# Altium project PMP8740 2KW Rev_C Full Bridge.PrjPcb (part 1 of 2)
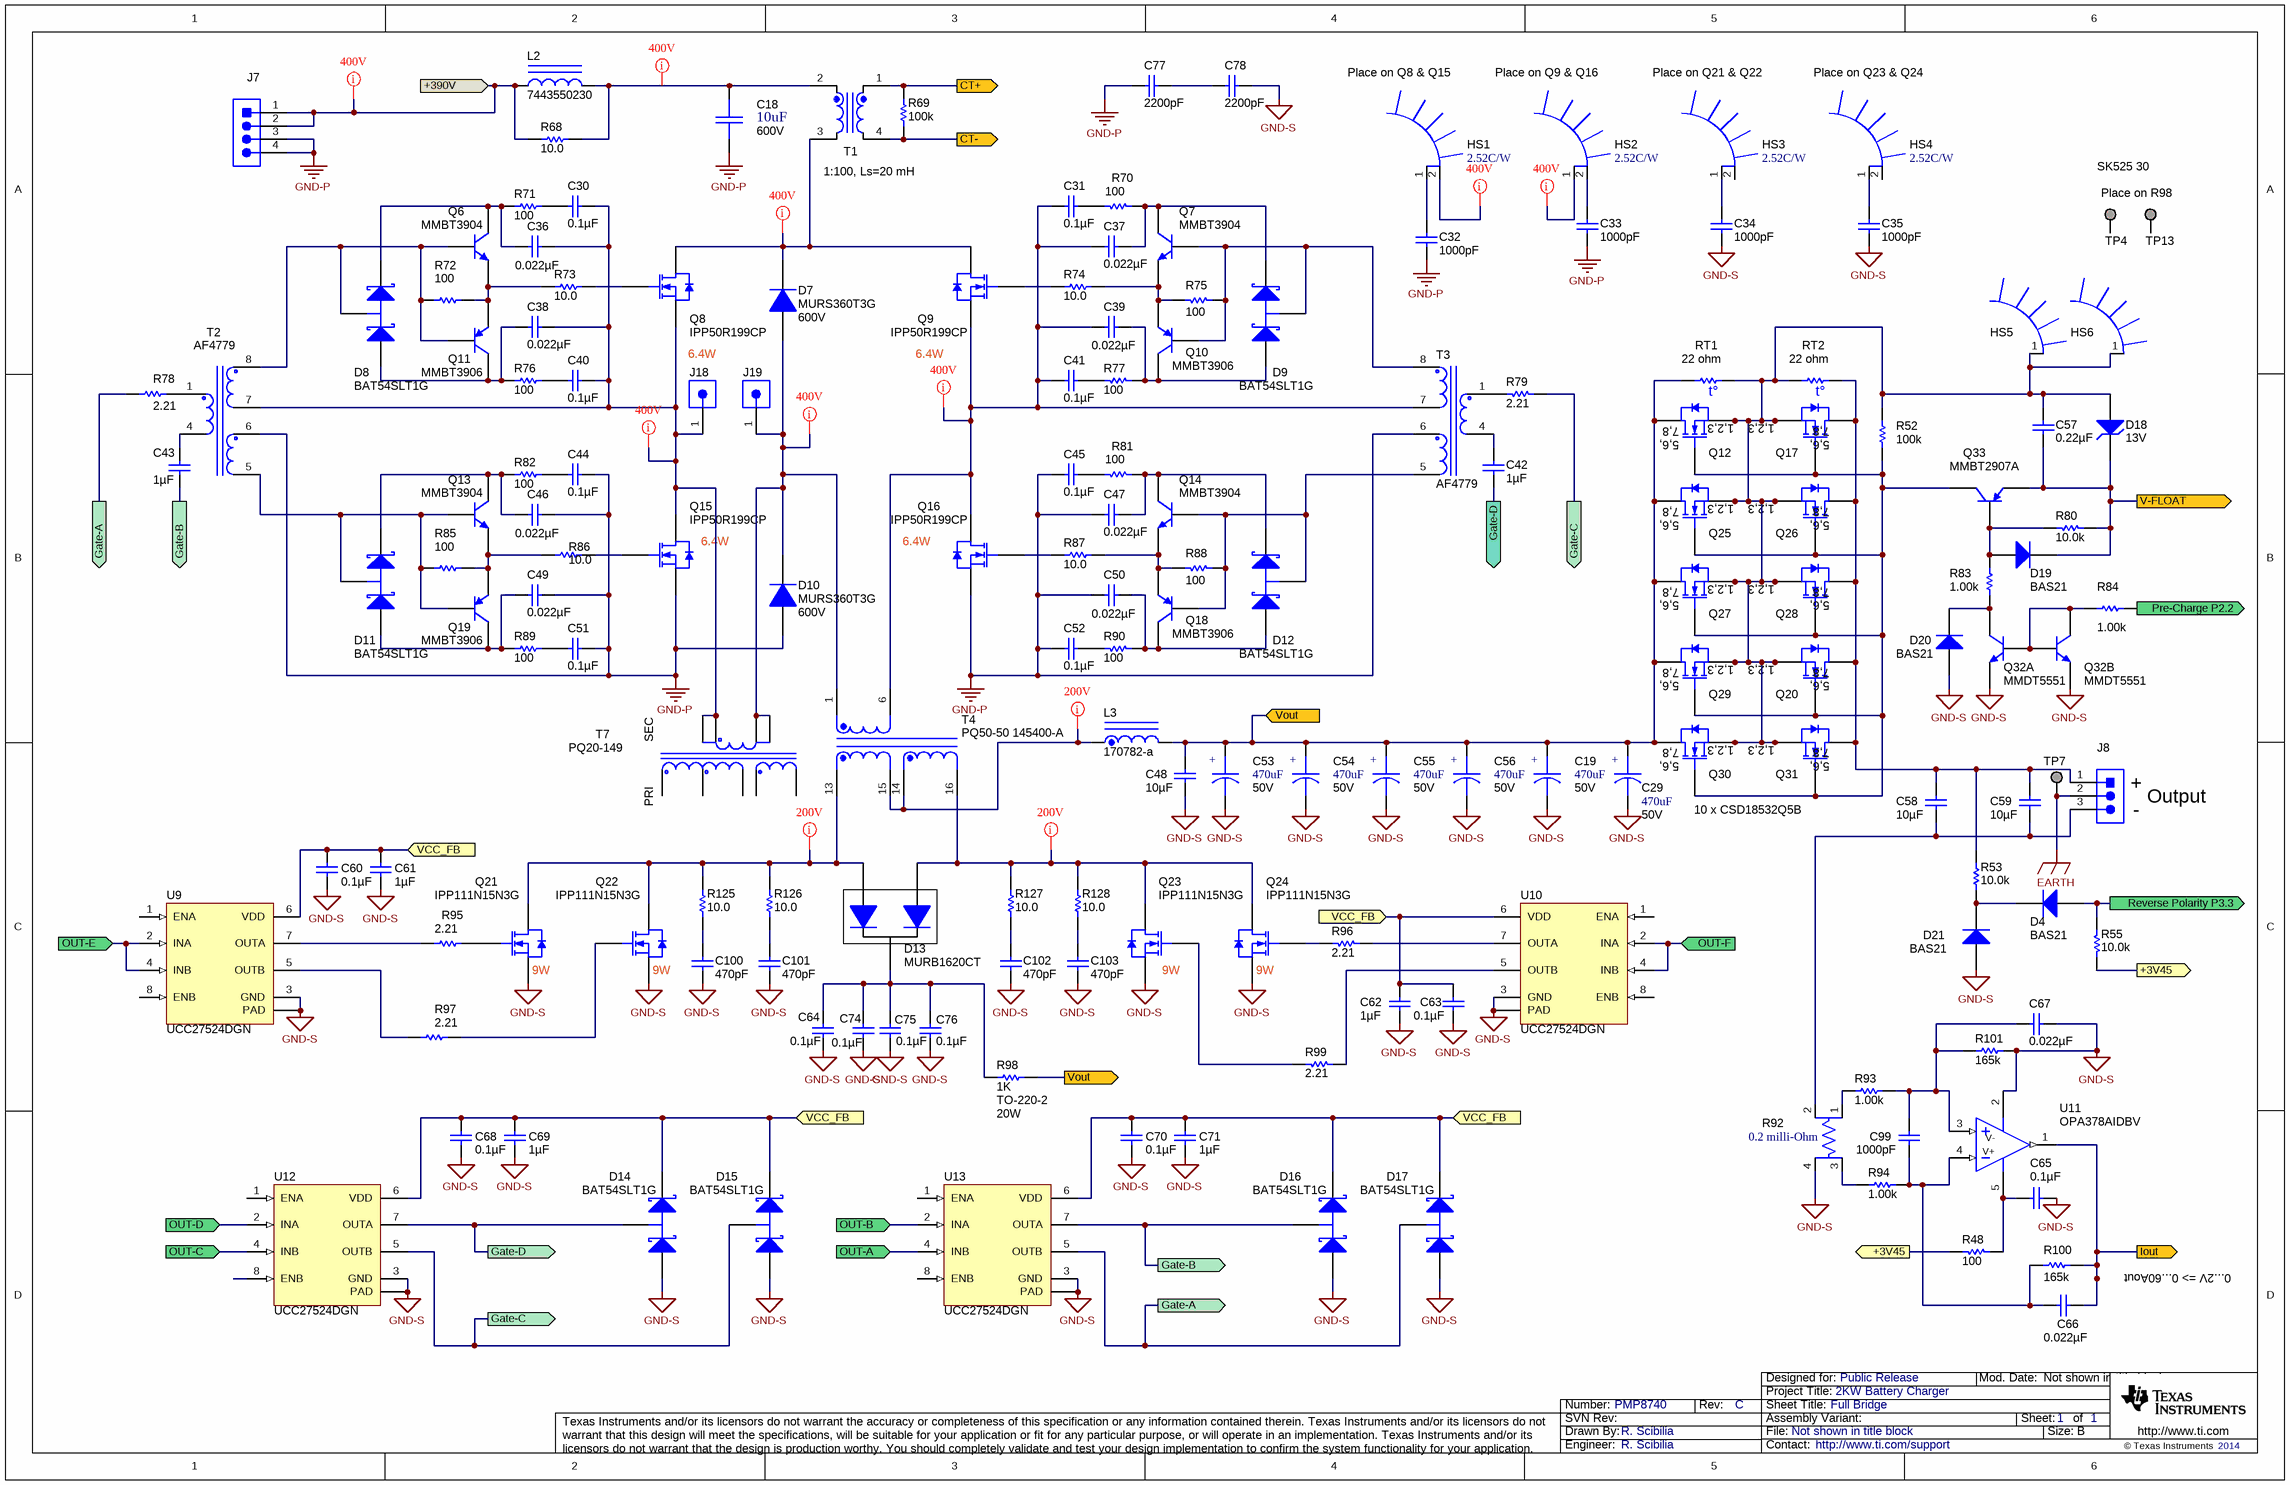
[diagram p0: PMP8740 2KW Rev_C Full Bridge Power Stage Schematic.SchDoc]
CopyrightYear: 2014; PCB_Layout: R. Scibilia; PCB_Rev: C; PRJ_Customer: Public Release; PRJ_Engineer: R. Scibilia; PRJ_Number: PMP8740; PRJ_Title: 2KW Battery Charger; SCH_Rev: C; TechSupport: http://www.ti.com/support
3 sheets, 355 parts. Net scope: flat (ports and power ports of the same name join across sheets).
Board file: PMP8740 2KW Rev_C Full Bridge Board.PcbDoc
Sheets:
  PMP8740 2KW Rev_C Full Bridge Power Stage Schematic.SchDoc
  PMP8740 2KW Rev_C Full Bridge Control Section-A Schematic.SchDoc
  PMP8740 2KW Rev_C Full Bridge Control Section-B Schematic.SchDoc

## Sheet PMP8740 2KW Rev_C Full Bridge Power Stage Schematic.SchDoc: Full Bridge
size 431 x 279 mm; Date: Not shown in title block; ApprovedBy: Not shown in title block; CheckedBy: Not shown in title block; Author: Not shown in title block; CompanyName: Not shown in title block; DrawnBy: R. Scibilia; Engineer: Not shown in title block; Organization: Not shown in title block; Address1: Not shown in title block; Address2: Not shown in title block; Address3: Not shown in title block; Address4: Not shown in title block; DocumentNumber: 1; Revision: Use project parameter SCH_Rev; SheetNumber: 1; SheetTotal: 1; PageSetup: Record=PageOptions|CenterHorizontal=True|CenterVertical=True|PrintScale=1.00|XCorrection=1.00|YCorrection=1.00|PrintKind=0|BorderSize=5000000|LeftOffset=0|BottomOffset=0|Orientation=2|PaperLength=1000|PaperWidth=1000|Scale=100|PaperSource=15|PrintQuality=600|MediaType=1|DitherType=10|PaperKind=Letter|PrintScaleMode=1

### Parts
C18  value 10uF  Voltage: 600V  [CAP_ECQE-1083MIL]  (hidden comment: C4AEHBU5100A11J)
C19  value 470uF  Voltage: 50V  [CAP_ZL-5X12.5MM]  (hidden comment: EKZM500ESS471MK20S)
C29  value 470uF  Voltage: 50V  [CAP_ZL-5X12.5MM]  (hidden comment: EKZM500ESS471MK20S)
C30  ValueDisplayed: 0.1µF  [0603]  (hidden comment: C1608X7R1H104K)
C31  ValueDisplayed: 0.1µF  [0603]  (hidden comment: C1608X7R1H104K)
C32  ValueDisplayed: 1000pF  [1206]  (hidden comment: CC1206KKX7RCBB102)
C33  ValueDisplayed: 1000pF  [1206]  (hidden comment: CC1206KKX7RCBB102)
C34  ValueDisplayed: 1000pF  [1206]  (hidden comment: CC1206KKX7RCBB102)
C35  ValueDisplayed: 1000pF  [1206]  (hidden comment: CC1206KKX7RCBB102)
C36  ValueDisplayed: 0.022µF  [0603]  (hidden comment: C1608X7R2A223K)
C37  ValueDisplayed: 0.022µF  [0603]  (hidden comment: C1608X7R2A223K)
C38  ValueDisplayed: 0.022µF  [0603]  (hidden comment: C1608X7R2A223K)
C39  ValueDisplayed: 0.022µF  [0603]  (hidden comment: C1608X7R2A223K)
C40  ValueDisplayed: 0.1µF  [0603]  (hidden comment: C1608X7R1H104K)
C41  ValueDisplayed: 0.1µF  [0603]  (hidden comment: C1608X7R1H104K)
C42  ValueDisplayed: 1µF  [0603]  (hidden comment: C1608X7R1E105K080AB)
C43  ValueDisplayed: 1µF  [0603]  (hidden comment: C1608X7R1E105K080AB)
C44  ValueDisplayed: 0.1µF  [0603]  (hidden comment: C1608X7R1H104K)
C45  ValueDisplayed: 0.1µF  [0603]  (hidden comment: C1608X7R1H104K)
C46  ValueDisplayed: 0.022µF  [0603]  (hidden comment: C1608X7R2A223K)
C47  ValueDisplayed: 0.022µF  [0603]  (hidden comment: C1608X7R2A223K)
C48  ValueDisplayed: 10µF  [1210]  (hidden comment: GRM32ER71H106KA12L)
C49  ValueDisplayed: 0.022µF  [0603]  (hidden comment: C1608X7R2A223K)
C50  ValueDisplayed: 0.022µF  [0603]  (hidden comment: C1608X7R2A223K)
C51  ValueDisplayed: 0.1µF  [0603]  (hidden comment: C1608X7R1H104K)
C52  ValueDisplayed: 0.1µF  [0603]  (hidden comment: C1608X7R1H104K)
C53  value 470uF  Voltage: 50V  [CAP_ZL-5X12.5MM]  (hidden comment: EKZM500ESS471MK20S)
C54  value 470uF  Voltage: 50V  [CAP_ZL-5X12.5MM]  (hidden comment: EKZM500ESS471MK20S)
C55  value 470uF  Voltage: 50V  [CAP_ZL-5X12.5MM]  (hidden comment: EKZM500ESS471MK20S)
C56  value 470uF  Voltage: 50V  [CAP_ZL-5X12.5MM]  (hidden comment: EKZM500ESS471MK20S)
C57  ValueDisplayed: 0.22µF  [0805_HV]  (hidden comment: C2012X7R1E224K)
C58  ValueDisplayed: 10µF  [1210]  (hidden comment: GRM32ER71H106KA12L)
C59  ValueDisplayed: 10µF  [1210]  (hidden comment: GRM32ER71H106KA12L)
C60  ValueDisplayed: 0.1µF  [0603]  (hidden comment: C1608X7R1H104K)
C61  ValueDisplayed: 1µF  [0603]  (hidden comment: C1608X7R1E105K080AB)
C62  ValueDisplayed: 1µF  [0603]  (hidden comment: C1608X7R1E105K080AB)
C63  ValueDisplayed: 0.1µF  [0603]  (hidden comment: C1608X7R1H104K)
C64  ValueDisplayed: 0.1µF  [1206]  (hidden comment: C3216X7R2E104K)
C65  ValueDisplayed: 0.1µF  [0603]  (hidden comment: C1608X7R1H104K)
C66  ValueDisplayed: 0.022µF  [0603]  (hidden comment: C1608X7R2A223K)
C67  ValueDisplayed: 0.022µF  [0603]  (hidden comment: C1608X7R2A223K)
C68  ValueDisplayed: 0.1µF  [0603]  (hidden comment: C1608X7R1H104K)
C69  ValueDisplayed: 1µF  [0603]  (hidden comment: C1608X7R1E105K080AB)
C70  ValueDisplayed: 0.1µF  [0603]  (hidden comment: C1608X7R1H104K)
C71  ValueDisplayed: 1µF  [0603]  (hidden comment: C1608X7R1E105K080AB)
C74  ValueDisplayed: 0.1µF  [1206]  (hidden comment: C3216X7R2E104K)
C75  ValueDisplayed: 0.1µF  [1206]  (hidden comment: C3216X7R2E104K)
C76  ValueDisplayed: 0.1µF  [1206]  (hidden comment: C3216X7R2E104K)
C77  ValueDisplayed: 2200pF  [CAPRD1000W60D900H1200]  (hidden comment: DE1E3KX222MA4BL01)
C78  ValueDisplayed: 2200pF  [CAPRD1000W60D900H1200]  (hidden comment: DE1E3KX222MA4BL01)
C99  ValueDisplayed: 1000pF  [0603]  (hidden comment: C1608C0G1H102J)
C100  ValueDisplayed: 470pF  [1206]  (hidden comment: VJ1206Y471KBEAT4X)
C101  ValueDisplayed: 470pF  [1206]  (hidden comment: VJ1206Y471KBEAT4X)
C102  ValueDisplayed: 470pF  [1206]  (hidden comment: VJ1206Y471KBEAT4X)
C103  ValueDisplayed: 470pF  [1206]  (hidden comment: VJ1206Y471KBEAT4X)
D4  value BAS21  [SOT-23]  (hidden comment: BAS21-7-F)
D7  MURS360T3G  value 600V  [SMC]
D8  BAT54SLT1G  [SOT-23]
D9  BAT54SLT1G  [SOT-23]
D10  MURS360T3G  value 600V  [SMC]
D11  BAT54SLT1G  [SOT-23]
D12  BAT54SLT1G  [SOT-23]
D13  value MURB1620CT  [DDPAK]  (hidden comment: VS-MURB1620CTPBF)
D14  BAT54SLT1G  [SOT-23]
D15  BAT54SLT1G  [SOT-23]
D16  BAT54SLT1G  [SOT-23]
D17  BAT54SLT1G  [SOT-23]
D18  value 13V  [SOD-123]  (hidden comment: MMSZ5243B-7-F)
D19  value BAS21  [SOT-23]  (hidden comment: BAS21-7-F)
D20  value BAS21  [SOT-23]  (hidden comment: BAS21-7-F)
D21  value BAS21  [SOT-23]  (hidden comment: BAS21-7-F)
HS1  value 2.52C/W  [HEATSINK_780603B0200]  (hidden comment: HEATSINK_780603B0200)
HS2  value 2.52C/W  [HEATSINK_780603B0200]  (hidden comment: HEATSINK_780603B0200)
HS3  value 2.52C/W  [HEATSINK_780603B0200]  (hidden comment: HEATSINK_780603B0200)
HS4  value 2.52C/W  [HEATSINK_780603B0200]  (hidden comment: HEATSINK_780603B0200)
HS5  HEATSINK_7109D  [HEATSINK_7109D]  (value not drawn)
HS6  HEATSINK_7109D  [HEATSINK_7109D]  (value not drawn)
J7  0015244557  [CONN_0015244557]  (value not drawn)
J8  1762754  [Phoenix_1762754]  (value not drawn)
J18  09 08 000 6124  [Han-FastLock_09080006124]  (value not drawn)
J19  09 08 000 6124  [Han-FastLock_09080006124]  (value not drawn)
L2  7443550230  [WE-HCA2]
L3  170782-a  [170782-a]
Q6  MMBT3904  [SOT-23]
Q7  MMBT3904  [SOT-23]
Q8  IPP50R199CP  [TO-220AB]
Q9  IPP50R199CP  [TO-220AB]
Q10  MMBT3906  [SOT-23]
Q11  MMBT3906  [SOT-23]
Q12  CSD18532Q5B  [TRANS_NexFET_Q5B]  (value not drawn)
Q13  MMBT3904  [SOT-23]
Q14  MMBT3904  [SOT-23]
Q15  IPP50R199CP  [TO-220AB]
Q16  IPP50R199CP  [TO-220AB]
Q17  CSD18532Q5B  [TRANS_NexFET_Q5B]  (value not drawn)
Q18  MMBT3906  [SOT-23]
Q19  MMBT3906  [SOT-23]
Q20  CSD18532Q5B  [TRANS_NexFET_Q5B]  (value not drawn)
Q21  IPP111N15N3G  [TO-220AB]
Q22  IPP111N15N3G  [TO-220AB]
Q23  IPP111N15N3G  [TO-220AB]
Q24  IPP111N15N3G  [TO-220AB]
Q25  CSD18532Q5B  [TRANS_NexFET_Q5B]  (value not drawn)
Q26  CSD18532Q5B  [TRANS_NexFET_Q5B]  (value not drawn)
Q27  CSD18532Q5B  [TRANS_NexFET_Q5B]  (value not drawn)
Q28  CSD18532Q5B  [TRANS_NexFET_Q5B]  (value not drawn)
Q29  CSD18532Q5B  [TRANS_NexFET_Q5B]  (value not drawn)
Q30  CSD18532Q5B  [TRANS_NexFET_Q5B]  (value not drawn)
Q31  CSD18532Q5B  [TRANS_NexFET_Q5B]  (value not drawn)
Q32  MMDT5551  [SOT-363]  (parts A,B of 2)
Q33  MMBT2907A  [SOT-23]
R48  value 100  [0603]  (hidden comment: CRCW0603100RFKEA)
R52  value 100k  [0603]  (hidden comment: CRCW0603100KFKEA)
R53  value 10.0k  [0805_HV]  (hidden comment: CRCW080510K0FKEA)
R55  value 10.0k  [0603]  (hidden comment: CRCW060310K0FKEA)
R68  ValueDisplayed: 10.0  [2010]  (hidden comment: CRCW201010R0FKEF)
R69  value 100k  [0805_HV]  (hidden comment: CRCW0805100KJNEA)
R70  value 100  [0603]  (hidden comment: CRCW0603100RFKEA)
R71  value 100  [0603]  (hidden comment: CRCW0603100RFKEA)
R72  value 100  [0603]  (hidden comment: CRCW0603100RFKEA)
R73  ValueDisplayed: 10.0  [1206]  (hidden comment: CRCW120610R0FKEA)
R74  ValueDisplayed: 10.0  [1206]  (hidden comment: CRCW120610R0FKEA)
R75  value 100  [0603]  (hidden comment: CRCW0603100RFKEA)
R76  value 100  [0603]  (hidden comment: CRCW0603100RFKEA)
R77  value 100  [0603]  (hidden comment: CRCW0603100RFKEA)
R78  value 2.21  [1206]  (hidden comment: CRCW12062R21FKEA)
R79  value 2.21  [1206]  (hidden comment: CRCW12062R21FKEA)
R80  value 10.0k  [0603]  (hidden comment: CRCW060310K0FKEA)
R81  value 100  [0603]  (hidden comment: CRCW0603100RFKEA)
R82  value 100  [0603]  (hidden comment: CRCW0603100RFKEA)
R83  value 1.00k  [0603]  (hidden comment: CRCW06031K00FKEA)
R84  value 1.00k  [0603]  (hidden comment: CRCW06031K00FKEA)
R85  value 100  [0603]  (hidden comment: CRCW0603100RFKEA)
R86  ValueDisplayed: 10.0  [1206]  (hidden comment: CRCW120610R0FKEA)
R87  ValueDisplayed: 10.0  [1206]  (hidden comment: CRCW120610R0FKEA)
R88  value 100  [0603]  (hidden comment: CRCW0603100RFKEA)
R89  value 100  [0603]  (hidden comment: CRCW0603100RFKEA)
R90  value 100  [0603]  (hidden comment: CRCW0603100RFKEA)
R92  value 0.2 milli-Ohm  [CSM-3637]  (hidden comment: BVR-Z-R0002-1.0)
R93  value 1.00k  [0603]  (hidden comment: CRCW06031K00FKEA)
R94  value 1.00k  [0603]  (hidden comment: CRCW06031K00FKEA)
R95  value 2.21  [1206]  (hidden comment: CRCW12062R21FKEA)
R96  value 2.21  [1206]  (hidden comment: CRCW12062R21FKEA)
R97  value 2.21  [1206]  (hidden comment: CRCW12062R21FKEA)
R98  value 1K  Value2: 20W  [TO-220-2]  (hidden comment: RTO020F10000JTE3)
R99  value 2.21  [1206]  (hidden comment: CRCW12062R21FKEA)
R100  value 165k  [0603]  (hidden comment: CRCW0603165KFKEA)
R101  value 165k  [0603]  (hidden comment: CRCW0603165KFKEA)
R125  ValueDisplayed: 10.0  [2010]  (hidden comment: CRCW201010R0FKEF)
R126  ValueDisplayed: 10.0  [2010]  (hidden comment: CRCW201010R0FKEF)
R127  ValueDisplayed: 10.0  [2010]  (hidden comment: CRCW201010R0FKEF)
R128  ValueDisplayed: 10.0  [2010]  (hidden comment: CRCW201010R0FKEF)
RT1  value 22 ohm  [S153]  (hidden comment: PTCCL09H171HBE)
RT2  value 22 ohm  [S153]  (hidden comment: PTCCL09H171HBE)
T1  value 1:100, Ls=20 mH  [XFMR_CS4200V-01L]  (hidden comment: CS4100V-01L)
T2  AF4779  [XFMR_VITEC-492x472x452]
T3  AF4779  [XFMR_VITEC-492x472x452]
T4  PQ50-50 145400-A  [Kaschke_PQ50-50 145400-A]
T7  PQ20-149  [XFMR_PQ20-149]
TP4  Suggest using a net name here  [CONN_8600-0-05-80-00-00-03-0]  (value not drawn)
TP7  Suggest using a net name here  [CONN_8600-0-05-80-00-00-03-0]  (value not drawn)
TP13  Suggest using a net name here  [CONN_8600-0-05-80-00-00-03-0]  (value not drawn)
U9  UCC27524DGN  [DGN0008D_N]
U10  UCC27524DGN  [DGN0008D_N]
U11  OPA378AIDBV  [DBV0005A_N]
U12  UCC27524DGN  [DGN0008D_N]
U13  UCC27524DGN  [DGN0008D_N]

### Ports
+3V45, +390V, CT+, CT-, Gate-A, Gate-B, Gate-C, Gate-D, Iout, OUT-A, OUT-B, OUT-C, OUT-D, OUT-E, OUT-F, Pre-Charge P2.2, Reverse Polarity P3.3, V-FLOAT, VCC_FB, Vout

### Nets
EARTH: J8.2 TP7.1
GND-P: C18.2 C32.2 C33.2 C44.2 C45.2 C46.1 C47.1 C49.1 C50.1 C51.2 C52.2 C77.2 D10.2(A) J7.3 J7.4 Q15.3(S) Q16.3(S) T2.6 T3.6
GND-S: C19.2 C29.2 C34.2 C35.2 C48.2 C53.2 C54.2 C55.2 C56.2 C60.2 C61.2 C62.2 C63.2 C64.2 C65.2 C67.1 C68.2 C69.2 C70.2 C71.2 C74.2 C75.2 C76.2 C78.1 C100.2 C101.2 C102.2 C103.2 D14.1(A) D15.1(A) D16.1(A) D17.1(A) D20.1(A) D21.1(A) Q21.3(S) Q22.3(S) Q23.3(S) Q24.3(S) Q32.1(E) Q32.4(E) R92.4 R101.1 U9.3(GND) U9.9(PAD) U10.3(GND) U10.9(PAD) U11.2(V-) U12.3(GND) U12.9(PAD) U13.3(GND) U13.9(PAD)
+3V45: R48.2 R55.1 ; port +3V45
+390V: J7.1 J7.2 L2.1 R68.1 ; port +390V
CT+: R69.2 T1.1 ; port CT+
CT-: R69.1 T1.4 ; port CT-
Gate-A: D17.3(C) R78.1 U13.5(OUTB) ; port Gate-A
Gate-B: C43.2 D16.3(C) U13.7(OUTA) ; port Gate-B
Gate-C: D15.3(C) R79.1 U12.5(OUTB) ; port Gate-C
Gate-D: C42.2 D14.3(C) U12.7(OUTA) ; port Gate-D
Iout: C66.1 R100.1 U11.1(OUT) ; port Iout
OUT-A: U13.4(INB) ; port OUT-A
OUT-B: U13.2(INA) ; port OUT-B
OUT-C: U12.4(INB) ; port OUT-C
OUT-D: U12.2(INA) ; port OUT-D
OUT-E: U9.2(INA) U9.4(INB) ; port OUT-E
OUT-F: U10.2(INA) U10.4(INB) ; port OUT-F
Pre-Charge P2.2: R84.1 ; port Pre-Charge P2.2
Reverse Polarity P3.3: D4.1(A) R55.2 ; port Reverse Polarity P3.3
V-FLOAT: C57.2 D18.1(K) D19.3(K) Q33.2(E) R80.2 ; port V-FLOAT
VCC_FB: C60.1 C61.1 C62.1 C63.1 C68.1 C69.1 C70.1 C71.1 D14.2(K) D15.2(K) D16.2(K) D17.2(K) U9.6(VDD) U10.6(VDD) U12.6(VDD) U13.6(VDD) ; port VCC_FB
Vout: C19.1 C29.1 C48.1 C53.1 C54.1 C55.1 C56.1 L3.2 Q12.5(D) Q12.6(D) Q12.7(D) Q12.8(D) Q25.5(D) Q25.6(D) Q25.7(D) Q25.8(D) Q27.5(D) Q27.6(D) Q27.7(D) Q27.8(D) Q29.5(D) Q29.6(D) Q29.7(D) Q29.8(D) Q30.5(D) Q30.6(D) Q30.7(D) Q30.8(D) R98.2 RT1.1 ; port Vout
NetC18_1: C18.1 L2.2 R68.2 T1.2
NetC30_1: C30.1 R71.1
NetC30_2: C30.2 C36.1 C38.1 C40.2 J18.1 Q8.3(S) Q15.2(D) T2.7 T7.2 T7.3
NetC31_1: C31.1 R70.1
NetC31_2: C31.2 C37.1 C39.1 C41.2 Q9.3(S) Q16.2(D) T3.7 T4.6
NetC32_1: C32.1 HS1.1
NetC33_1: C33.1 HS2.2
NetC34_1: C34.1 HS3.1
NetC35_1: C35.1 HS4.1
NetC36_2: C36.2 D8.2(K) Q6.3(C) R71.2
NetC37_2: C37.2 D9.2(K) Q7.3(C) R70.2
NetC38_2: C38.2 D8.1(A) Q11.3(C) R76.2
NetC39_2: C39.2 D9.1(A) Q10.3(C) R77.2
NetC40_1: C40.1 R76.1
NetC41_1: C41.1 R77.1
NetC42_1: C42.1 T3.4
NetC43_1: C43.1 T2.4
NetC44_1: C44.1 R82.1
NetC45_1: C45.1 R81.1
NetC46_2: C46.2 D11.2(K) Q13.3(C) R82.2
NetC47_2: C47.2 D12.2(K) Q14.3(C) R81.2
NetC49_2: C49.2 D11.1(A) Q19.3(C) R89.2
NetC50_2: C50.2 D12.1(A) Q18.3(C) R90.2
NetC51_1: C51.1 R89.1
NetC52_1: C52.1 R90.1
NetC57_1: C57.1 D18.2(A) HS5.1 HS6.1 Q12.1(S) Q12.2(S) Q12.3(S) Q17.1(S) Q17.2(S) Q17.3(S) Q20.1(S) Q20.2(S) Q20.3(S) Q25.1(S) Q25.2(S) Q25.3(S) Q26.1(S) Q26.2(S) Q26.3(S) Q27.1(S) Q27.2(S) Q27.3(S) Q28.1(S) Q28.2(S) Q28.3(S) Q29.1(S) Q29.2(S) Q29.3(S) Q30.1(S) Q30.2(S) Q30.3(S) Q31.1(S) Q31.2(S) Q31.3(S) R52.2 RT1.2 RT2.1
NetC58_1: C58.1 C59.1 J8.1 Q17.5(D) Q17.6(D) Q17.7(D) Q17.8(D) Q20.5(D) Q20.6(D) Q20.7(D) Q20.8(D) Q26.5(D) Q26.6(D) Q26.7(D) Q26.8(D) Q28.5(D) Q28.6(D) Q28.7(D) Q28.8(D) Q31.5(D) Q31.6(D) Q31.7(D) Q31.8(D) R53.2 RT2.2
NetC58_2: C58.2 C59.2 J8.3 R92.2
NetC64_1: C64.1 C74.1 C75.1 C76.1 D13.4(K) R98.1
NetC65_1: C65.1 R48.1 U11.5(V+)
NetC66_2: C66.2 C99.2 R94.1 R100.2 U11.4(IN-)
NetC67_2: C67.2 C99.1 R93.1 R101.2 U11.3(IN+)
NetC77_1: C77.1 C78.2
NetC100_1: C100.1 R125.1
NetC101_1: C101.1 R126.1
NetC102_1: C102.1 R127.1
NetC103_1: C103.1 R128.1
NetD4_3: D4.3(K) D21.3(K) R53.1
NetD7_1: D7.1(K) Q8.2(D) Q9.2(D) T1.3
NetD7_2: D7.2(A) D10.1(K) J19.1 T4.1 T7.4 T7.5
NetD8_3: D8.3(C) Q6.1(B) Q11.1(B) R72.1 T2.8
NetD9_3: D9.3(C) Q7.1(B) Q10.1(B) R75.1 T3.8
NetD11_3: D11.3(C) Q13.1(B) Q19.1(B) R85.1 T2.5
NetD12_3: D12.3(C) Q14.1(B) Q18.1(B) R88.1 T3.5
NetD13_1: D13.1(A) Q21.2(D) Q22.2(D) R125.2 R126.2 T4.13
NetD13_3: D13.3(A) Q23.2(D) Q24.2(D) R127.2 R128.2 T4.16
NetD19_1: D19.1(A) Q33.1(B) R80.1 R83.2
NetD20_3: D20.3(K) Q32.3(C) R83.1
NetL3_1: L3.1 T4.14 T4.15
NetQ6_2: Q6.2(E) Q11.2(E) R72.2 R73.1
NetQ7_2: Q7.2(E) Q10.2(E) R74.1 R75.2
NetQ8_1: Q8.1(G) R73.2
NetQ9_1: Q9.1(G) R74.2
NetQ12_4: Q12.4(G) Q17.4(G) Q20.4(G) Q25.4(G) Q26.4(G) Q27.4(G) Q28.4(G) Q29.4(G) Q30.4(G) Q31.4(G) Q33.3(C) R52.1
NetQ13_2: Q13.2(E) Q19.2(E) R85.2 R86.1
NetQ14_2: Q14.2(E) Q18.2(E) R87.1 R88.2
NetQ15_1: Q15.1(G) R86.2
NetQ16_1: Q16.1(G) R87.2
NetQ21_1: Q21.1(G) R95.2
NetQ22_1: Q22.1(G) R97.1
NetQ23_1: Q23.1(G) R99.1
NetQ24_1: Q24.1(G) R96.2
NetQ32_2: Q32.2(B) Q32.5(B) Q32.6(C) R84.2
NetR78_2: R78.2 T2.1
NetR79_2: R79.2 T3.1
NetR92_1: R92.1 R93.2
NetR92_3: R92.3 R94.2
NetR95_1: R95.1 U9.7(OUTA)
NetR96_1: R96.1 U10.7(OUTA)
NetR97_2: R97.2 U9.5(OUTB)
NetR99_2: R99.2 U10.5(OUTB)

Not connected (* = marked no-connect by the designer): HS1 2; HS2 1; HS3 2; HS4 2; T7 8 9 10 11 12; TP4 1; TP13 1; U9 1(ENA) 8(ENB); U10 1(ENA) 8(ENB); U12 1(ENA) 8(ENB); U13 1(ENA) 8(ENB)

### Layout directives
rule Clearance Constraint [Clearance = 40mil]: +390V, NetC18_1, NetC30_2, NetC31_2, NetD7_1, NetD7_2, NetHS1_2, NetHS2_1
rule Clearance Constraint [Clearance = 20mil]: NetD13_1, NetD13_3, NetL3_1

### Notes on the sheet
- Place on Q8 & Q15
- Place on Q9 & Q16
- Place on Q21 & Q22
- Place on Q23 & Q24
- SK525 30
- Place on R98
- 6.4W
- (near Q15) 6.4W
- (near Q16) 6.4W
- 10 x CSD18532Q5B
- (near J8) +
- (near J8) -
- (near J8) Output
- (near Q21) 9W
- (near Q22) 9W
- (near Q23) 9W
- (near Q24) 9W
- 0...2V => 0...60Aout

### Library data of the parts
C18 = CAP_ECQ-E6225KF: Capacitor, Polyester Film, vvV, ±10%; Manufacturer: KEMET; Area: 998,298
C19 C29 C53-C56 = CAP_ZL_12.5MM_SERIES: Capacitor, Electrolytic, KZM series, 50V, 105C, 20%; Manufacturer: Nippon Chemi-Con; Area: 214,008
C30 C31 C40 C41 C44 C45 C51 C52 C60 C63 C65 C68 C70 = C1608X7R1H104K: CAP, CERM, 0.1uF, 50V, +/-10%, X7R, 0603; Manufacturer: TDK; Polarized: N; CompType: Capacitor; U/M: EA; Cap_F: 0.0000001; Tolerance_%: 10; ESR_Ohm: 0.017; Value1: 0.017 ohm; VDC_V: 50; TaMin_C: -55; TaMax_C: 125
C32-C35 = CC1206KKX7RCBB102: CAP, CERM, 1000pF, 1000V, +/-10%, X7R, 1206; Manufacturer: Yageo America; Polarized: N; CompType: Capacitor; U/M: EA; Cap_F: 0.000000001; Tolerance_%: 10; Value1: Unknown; VDC_V: 1000; TaMin_C: -55; TaMax_C: 125
C36-C39 C46 C47 C49 C50 C66 C67 = C1608X7R2A223K: CAP, CERM, 0.022uF, 100V, +/-10%, X7R, 0603; Manufacturer: TDK; Polarized: N; CompType: Capacitor; U/M: EA; Cap_F: 0.000000022; Tolerance_%: 10; ESR_Ohm: 0.037; Value1: 0.037 ohm; VDC_V: 100; TaMin_C: -55; TaMax_C: 125
C42 C43 C61 C62 C69 C71 = C1608X7R1E105K080AB: CAP, CERM, 1uF, 25V, +/-10%, X7R, 0603; Manufacturer: TDK; Polarized: N; CompType: Capacitor; U/M: EA; Cap_F: 0.000001; Tolerance_%: 10; Value1: Unknown; VDC_V: 25; TaMin_C: -55; TaMax_C: 125
C48 C58 C59 = GRM32ER71H106KA12L: CAP, CERM, 10uF, 50V, +/-10%, X7R, 1210; Manufacturer: MuRata; Polarized: N; CompType: Capacitor; U/M: EA; Cap_F: 0.00001; Tolerance_%: 10; Value1: Unknown; VDC_V: 50; TaMin_C: -55; TaMax_C: 125
C57 = C2012X7R1E224K: CAP, CERM, 0.22 µF, 25 V, +/- 10%, X7R, 0805; Manufacturer: TDK; Polarized: N; CompType: Capacitor; Value: 0.22uF; U/M: EA; Cap_F: 0.00000022; Tolerance_%: 10; ESR_ohm: 0.0117; Value1: 0.0117 ohm; VDC_V: 25; Value2: 25V; TaMin_C: -55; TaMax_C: 125; Cap_Case: 0805
C64 C74-C76 = C3216X7R2E104K: CAP, CERM, 0.1uF, 250V, +/-10%, X7R, 1206; Manufacturer: TDK; Polarized: N; CompType: Capacitor; U/M: EA; Cap_F: 0.0000001; Tolerance_%: 10; ESR_Ohm: 0.0217; Value1: 0.0217 ohm; VDC_V: 250; TaMin_C: -55; TaMax_C: 125
C77 C78 = DE1E3KX222MA4BL01: CAP, CERM, 2200pF, 250V, +/-20%, E, Cap, 7x12x9 mm; Manufacturer: MuRata; Polarized: N; CompType: Capacitor; U/M: EA; Cap_F: 0.0000000022; Tolerance_%: 20; Value1: Unknown; VDC_V: 250; TaMin_C: -25; TaMax_C: 85
C99 = C1608C0G1H102J: CAP, CERM, 1000 pF, 50 V, +/- 5%, C0G/NP0, 0603; Manufacturer: TDK; Polarized: N; CompType: Capacitor; Value: 1000pF; U/M: EA; Cap_F: 0.000000001; Tolerance_%: 5; ESR_ohm: 0.0563; Value1: 0.0563 ohm; VDC_V: 50; Value2: 50V; TaMin_C: -55; TaMax_C: 125
C100-C103 = VJ1206Y471KBEAT4X: CAP, CERM, 470 pF, 500 V, +/- 10%, X7R, 1206; Manufacturer: Vishay-Vitramon; Polarized: N; CompType: Capacitor; Value: 470pF; U/M: EA; Cap_F: 0.00000000047; Tolerance_%: 10; Value1: Unknown; VDC_V: 500; Value2: 500V; TaMin_C: -55; TaMax_C: 125
D4 D19-D21 = BAS21-7-F: Diode, Switching, 200V, 0.2A, SOT-23; Manufacturer: Diodes Inc.; U/M: EA; Vf_V: 1.25; Value2: 1.25V; Io_A: 0.2; Vr_V: 200; TJmax_C: 150; RJC_CperW: 500
D7 D10 = MURS360T3G: Diode, Ultrafast, 600V, 3A, SMC; Manufacturer: ON Semiconductor; U/M: EA; Vf_V: 1.25; Value2: 1.25V; Io_A: 3; Vr_V: 600; TJmax_C: 175; RJC_CperW: 11
D8 D9 D11 D12 D14-D17 = BAT54SLT1G: Diode, Schottky, 30V, 0.2A, SOT-23; Manufacturer: ON Semiconductor; U/M: EA; Vf_V: 0.8; Value2: 0.8V; Io_A: 0.2; Vr_V: 30; TJmax_C: 150
D13 = VS-MURB1620CTPBF: Diode, Ultrafast, 200V, 8A, DDPAK; Manufacturer: Vishay-Semiconductor; RJC_CperW: 3; Vf_V: 0.975; Io_A: 8; Vr_V: 200; TJMax_C: 150; U/M: EA; Value2: 0.975V
D18 = MMSZ5243B-7-F: Diode, Zener, 13 V, 500 mW, SOD-123; Manufacturer: Diodes Inc.; SymbolCreator: a0412235; U/M: EA; Power_W: 0.5; Vz_V: 13; Value1: 0.5W; RJA_CperW: 350
HS1-HS4 = HEATSINK_780603B0200: Heatsink,  Vertical-mount; Manufacturer: Fischer; PartNumber: SK 481-50; area: 2480100
HS5 HS6 = HEATSINK_7109D: Heatsink, SMT; Manufacturer: Aavid; PartNumber: 7109D; area: 803400; Value: 7109D
J7 = 0015244557: Header, 4POS, 200mil, Vertical, Tin, TH; Manufacturer: Molex; SymbolCreator: a0412235; CompType: Connector; U/M: EA
J8 = 1762754: Header (shrouded), 15 mm, 3x3, R/A, TH; Manufacturer: Phoenix Contact; SymbolCreator: a0799628; U/M: EA
J18 J19 = 09 08 000 6124: Power Connector, 8AWG, SILVER W/PIN, TH; Manufacturer: Harting; SymbolCreator: a0412235; U/M: EA
L2 = 7443550230: Inductor, Shielded Drum Core, WE-Perm, 2.3uH, 17A, 0.0037 ohm, SMD; Manufacturer: Wurth Elektronik eiSos; Ind_H: 2.3E-6; ValueDisplayed: 2.3µH; Imax_A: 17; Irms: 17.5A @ 50C rise; Isat: 17A @ 30% inductance drop; DCR_ohm: 0.0037; U/M: EA
L3 = 170782-a: Inductor, Wirewound, 7.9uH, 60A, SMD; Manufacturer: Kaschke Components; SymbolCreator: a0412235; Ind_H: 7.9E-6; ValueDisplayed: 7.9µH; Imax_A: 60; Irms: 60A @ C rise
Q6 Q7 Q13 Q14 = MMBT3904, Fairchild Semiconductor: Transistor, NPN, 40V, 0.2A, SOT-23; CompType: BJT; PNP: 0; NPN: 1; Vceo_V: 40; Vcesat1_V: 0.2; HfeMax: 300; TaMin_C: -55; TaMax_C: 150; U/M: EA
Q8 Q9 Q15 Q16 = IPP50R199CP: MOSFET, N-CH, 550V, 17A, TO-220AB; Manufacturer: Infineon Technologies; Alternate Manufacturer: None; U/M: EA; ChType: N; VdsMax_V: 550; Value1: ? ohm; Rdson45_Ohm: 0; Value2: 34 nC; QgTyp_nC: 34; Vgs_V: 20; IdsMax_A: 17
Q10 Q11 Q18 Q19 = MMBT3906, Fairchild Semiconductor: Transistor, PNP, 40V, 0.2A, SOT-23; CompType: BJT; PNP: 1; NPN: 0; Vceo_V: 40; Vcesat1_V: 0.25; IcRated_A: 0.2; HfeMax: 300; TaMin_C: -55; TaMax_C: 150; U/M: EA
Q12 Q17 Q25-Q28 Q30 Q31 = CSD18532Q5B: MOSFET, N-CH, 60V, 172A, SON 5x6mm; Manufacturer: Texas Instruments; Alternate Manufacturer: None; U/M: EA; ChType: N; VdsMax_V: 60; Value1: 3.3 ohm; Rdson45_Ohm: 3.3; Value2: 27 nC; QgTyp_nC: 27; Vgs_V: 1.6; IdsMax_A: 172
Q20 Q29 = CSD18532Q5B: MOSFET, N-CH, 60V, 172A, SON 5x6mm; Manufacturer: Texas Instruments; Alternate Manufacturer: None; U/M: EA; ChType: N; VdsMax_V: 60; Rdson45_Ohm: 3.3; Value2: 27 nC; QgTyp_nC: 27; Vgs_V: 1.6; IdsMax_A: 172
Q21-Q24 = IPP50R199CP: MOSFET, N-CH, 150V, 83A, TO-220AB; Manufacturer: Infineon Technologies; Alternate Manufacturer: None; U/M: EA; ChType: N; VdsMax_V: 550; Value1: ? ohm; Rdson45_Ohm: 0; Value2: 34 nC; QgTyp_nC: 34; Vgs_V: 20; IdsMax_A: 17
Q32 = MMDT3904-7-F, Diodes Inc.: Transistor, Dual NPN, 160 V, 0.2 A, SOT-363; SymbolCreator: a0411947; PNP: 0; NPN: 2; Vceo_V: 160; Vcesat1_V: 0.3; IcRated_A: 0.2; Value1: 0.2 A; HfeMax: 300; TaMin_C: -55; TaMax_C: 150; CompType: BJT; U/M: EA
Q33 = MMBT2907A, Fairchild Semiconductor: Transistor, PNP, 60 V, 0.8 A, SOT-23; CompType: BJT; PNP: 1; NPN: 0; Vceo_V: 60; Vcesat1_V: 1.6; Value: 60 V; IcRated_A: 0.8; Value1: 0.8 A; HfeMax: 300; TaMin_C: -55; TaMax_C: 150; U/M: EA
R48 R70-R72 R75-R77 R81 R82 R85 R88-R90 = CRCW0603100RFKEA: RES, 100 ohm, 1%, 0.1W, 0603; Manufacturer: Vishay-Dale; CompType: Resistor; Value_Code: 100R; Tolerance_%: 1; Power_W: 0.1; VDC_V: 75; TempCo: 100 ppm/C; EIA_Code: E96; U/M: EA
R52 = CRCW0603100KFKEA: RES, 100k ohm, 1%, 0.1W, 0603; Manufacturer: Vishay-Dale; CompType: Resistor; Res_ohm: 100000; Tolerance_%: 1; Power_W: 0.1; VDC_V: 75; TempCo: 100 ppm/C; EIA_Code: E96; U/M: EA
R53 = CRCW080510K0FKEA: RES, 10.0k ohm, 1%, 0.125W, 0805; Manufacturer: Vishay-Dale; CompType: Resistor; Res_ohm: 10000; Value_Code: 10k0; Tolerance_%: 1; Power_W: 0.125; VDC_V: 150; TempCo: 100 ppm/C; EIA_Code: E96; U/M: EA
R55 R80 = CRCW060310K0FKEA: RES, 10.0k ohm, 1%, 0.1W, 0603; Manufacturer: Vishay-Dale; CompType: Resistor; Res_ohm: 10000; Value_Code: 10k0; Tolerance_%: 1; Power_W: 0.1; VDC_V: 75; TempCo: 100 ppm/C; EIA_Code: E96; U/M: EA
R68 R125-R128 = CRCW201010R0FKEF: RES, 10.0, 1%, 0.75 W, 2010; Manufacturer: Vishay-Dale; CompType: Resistor; Value: 10.0; Res_ohm: 10; Value_Code: 10R0; Tolerance_%: 1; Power_W: 0.75; Value2: 0.75W; VDC_V: 400; TempCo: 100 ppm/C; EIA_Code: E96; U/M: EA
R69 = CRCW0805100KJNEA: RES, 100k ohm, 5%, 0.125W, 0805; Manufacturer: Vishay-Dale; CompType: Resistor; Res_ohm: 100000; Tolerance_%: 5; Power_W: 0.125; VDC_V: 150; TempCo: 200 ppm/C; EIA_Code: E24; U/M: EA
R73 R74 R86 R87 = CRCW120610R0FKEA: RES, 10.0, 1%, 0.25 W, 1206; Manufacturer: Vishay-Dale; CompType: Resistor; Value: 10.0; Res_ohm: 10; Value_Code: 10R0; Tolerance_%: 1; Power_W: 0.25; Value2: 0.25W; VDC_V: 200; TempCo: 100 ppm/C; EIA_Code: E96; U/M: EA
R78 R79 R95-R97 R99 = CRCW12062R21FKEA: RES, 2.21 ohm, 1%, 0.25W, 1206; Manufacturer: Vishay-Dale; CompType: Resistor; Value_Code: 2R21; Tolerance_%: 1; Power_W: 0.25; VDC_V: 200; TempCo: 100 ppm/C; EIA_Code: E96; U/M: EA
R83 R84 R93 R94 = CRCW06031K00FKEA: RES, 1.00k ohm, 1%, 0.1W, 0603; Manufacturer: Vishay-Dale; CompType: Resistor; Res_ohm: 1000; Value_Code: 1k00; Tolerance_%: 1; Power_W: 0.1; VDC_V: 75; TempCo: 100 ppm/C; EIA_Code: E96; U/M: EA
R92 = R-WSL3637: Resistor, precision shunt,  5W, 1%,; Manufacturer: Isabellenhuette; Area: 184900; Description: Resistor Pack,  xxW, yy%,
R98 = RTO020F680R0JTE3: RES, 1Kohm, 5%, 20W, TH; Manufacturer: Vishay-Dale; CompType: Resistor; Res_ohm: 680; Value_Code: 680R; Tolerance_%: 5; Power_W: 20; VDC_V: 500; TempCo: 150 ppm/C; EIA_Code: E24; U/M: EA
R100 R101 = CRCW0603165KFKEA: RES, 165k ohm, 1%, 0.1W, 0603; Manufacturer: Vishay-Dale; CompType: Resistor; Res_ohm: 165000; Tolerance_%: 1; Power_W: 0.1; VDC_V: 75; TempCo: 100 ppm/C; EIA_Code: E96; U/M: EA
RT1 RT2 = B57153S150M: Thermistor PTC, 15 ohm, 8.5mm Disc; Manufacturer: Vishay; CompType: ThermistorNTC; Tolerance_%: 20; Power_W: 1.4; TaMin_C: -55; TaMax_C: 170; U/M: EA
T1 = CS4200V-01L: Transformer , Current sense, 1:100, 20 mH, TH; Manufacturer: Coilcraft; SymbolCreator: a0799628; U/M: EA
T2 T3 = AF4779: Drive Gate Transformer, 900uH; Manufacturer: Vitec Corporation; SymbolCreator: a0799628; DCR_Ohm: 0.6; LeakageL: 0.35uH; Ind_H: 900.0E-6; U/M: EA
T4 = PQ50-50 145400-A: Transformer, 3.2mH, TH; Manufacturer: Kaschke Components; SymbolCreator: x0208326; U/M: EA
T7 = PQ20-149: Transformer, 300uH, TH; Manufacturer: Click Technology; SymbolCreator: a0411947; U/M: EA
TP4 TP7 TP13 = 8600-0-05-80-00-00-03-0: PCB Pin, solderless Pressfit, Tin over Nickel; Manufacturer: Mill-Max; CompType: PCB Pin; U/M: EA
U9 U10 U12 U13 = UCC27524DGN: Dual 5-A High-Speed Low-Side Gate Driver, DGN0008D; Alternate Manufacturer: None; Manufacturer: Texas Instruments; SymbolCreator: a0411947; CompType: IC; U/M: EA
U11 = OPA376AIDBV: Low-Noise, Low Quiescent Current, Precision Operational Amplifier e-trim Series, DBV0005A; Alternate Manufacturer: None; Manufacturer: Texas Instruments; CompType: IC; U/M: EA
